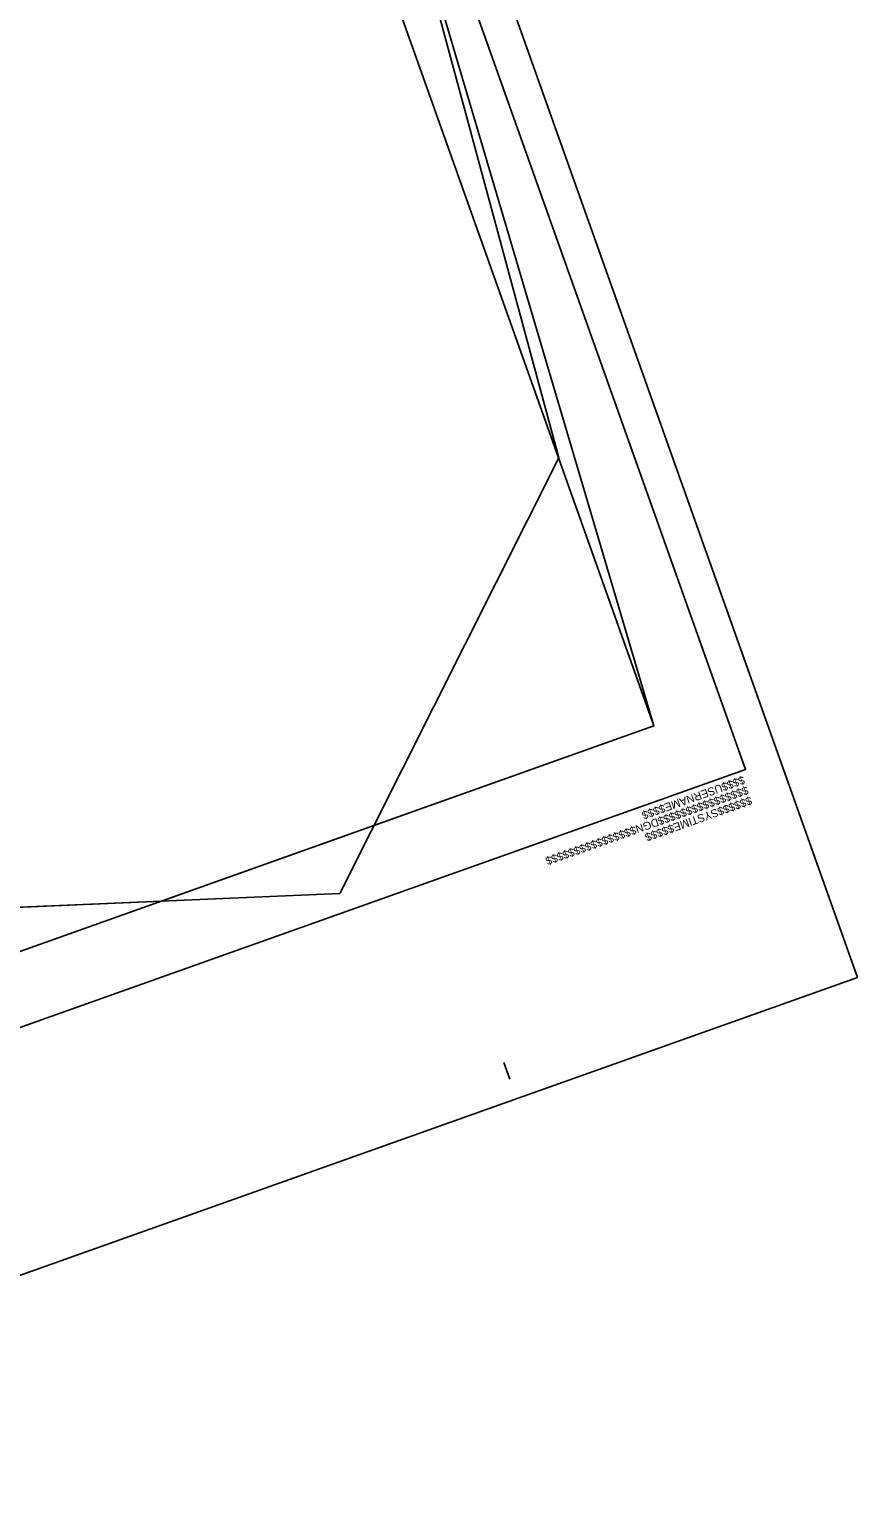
# Model space of a CAD drawing. Extents: x 1615843 to 1618439, y 899470 to 903922.
# Drawn here: x 1616867 to 1617445, y 901963 to 902993 of the extents above; entities that cross this region are included whole.
import ezdxf

# ---------------------------------------------------------------- set-up
doc = ezdxf.new("R2010")
doc.units = 0
for name, color, linetype in [('DEV BORDER CELL', 7, 'Continuous'), ('Matchline', 7, 'Continuous'), ('Scratch_Level_0', 7, 'Continuous'), ('Scratch_Level_5', 7, 'Continuous'), ('Sheet Clip Boundary CELL', 7, 'Continuous'), ('Sheet Plot Border Outside CELL', 7, 'Continuous')]:
    doc.layers.add(name, color=color, linetype=linetype)

msp = doc.modelspace()

# ---------------------------------------------------------------- linework, layer by layer
at = {"layer": 'DEV BORDER CELL'}
for p, q in [((1617366.7, 902476.5), (1617366.7, 902476.5)), ((1617202.1, 902260.4), (1617197.9, 902272.1))]:
    msp.add_line(p, q, dxfattribs=at)
msp.add_lwpolyline([(1615874.9, 903538.1), (1616377.3, 902124.8), (1617366.7, 902476.5), (1616864.2, 903889.8)], close=True, dxfattribs=at)
at = {"layer": 'Matchline'}
msp.add_line((1616959.1, 902384.7), (1616347.4, 902358.2), dxfattribs=at)
at = {"layer": 'Scratch_Level_0'}
msp.add_lwpolyline([(1615938.7, 903507.8), (1616407.7, 902188.6), (1617302.8, 902506.9), (1617008.4, 903334.9), (1616897, 903295.3), (1616722.4, 903786.4)], close=True, dxfattribs=at)
at = {"layer": 'Scratch_Level_5'}
for points in [[(1616347.4, 902358.2), (1615993.9, 903352.6), (1616755.4, 903693.5), (1617118.3, 903131.4), (1617302.8, 902506.9), (1616959.1, 902384.7)], [(1616705.5, 902373.7), (1616699.9, 902459), (1616686.6, 902573.2), (1616667, 902687.9), (1616638, 902809.4), (1616596.8, 902943.3), (1616589, 902949), (1616499.3, 903201.9), (1616504.1, 903203.6), (1616506.9, 903204.5), (1616400, 903496.4), (1616388.1, 903529.1), (1616755.4, 903693.5), (1617118.3, 903131.4), (1617302.8, 902506.9), (1616959.1, 902384.7)], [(1616699.3, 902373.4), (1616633.8, 902806.5), (1616631.9, 902813.2), (1616597.9, 902897.5), (1616599.3, 902920.4), (1616597.1, 902927), (1616370.6, 903502.2), (1616643.5, 903550.3), (1617118.3, 903131.4), (1617302.8, 902506.9), (1616959.1, 902384.7)]]:
    msp.add_lwpolyline(points, close=True, dxfattribs=at)
at = {"layer": 'Sheet Clip Boundary CELL'}
msp.add_lwpolyline([(1616920.6, 902383), (1616489.9, 902364.3), (1616361.8, 902926), (1616113.5, 903406.1), (1616903.3, 903759.8), (1617118.3, 903131.4), (1617236.3, 902694), (1617083.5, 902390)], close=True, dxfattribs=at)
at = {"layer": 'Sheet Plot Border Outside CELL'}
for points in [[(1617444.8, 902331.3), (1616879.4, 903921.8), (1615842.9, 903553.3), (1616408.4, 901962.8)], [(1617444.8, 902331.3), (1616408.4, 901962.8), (1615842.9, 903553.3), (1616879.4, 903921.8)]]:
    msp.add_lwpolyline(points, close=True, dxfattribs=at)

# ---------------------------------------------------------------- texts
at = {"layer": 'DEV BORDER CELL'}
for s, p in [('$$$$USERNAME$$$$', (1617365, 902472.1)), ('$$$$$$$$$$$$$$$$DGN$$$$$$$$$$$$$$$$', (1617367.5, 902465)), ('$$$$$$SYSTIME$$$$$', (1617370, 902457.8))]:
    msp.add_text(s, height=5.584, rotation=199.5707, dxfattribs=at).set_placement(p)

doc.saveas('drawing.dxf')
